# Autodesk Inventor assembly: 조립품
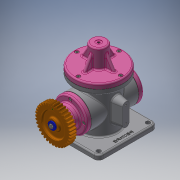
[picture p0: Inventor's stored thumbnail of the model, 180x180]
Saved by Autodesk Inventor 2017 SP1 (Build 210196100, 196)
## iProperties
Part Number: 조립품
Material: 일반
Document SubType Name: Assembly
Designer: 00-00
Author: 00-00
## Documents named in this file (21)
- C:\Users\00-00\Desktop\601206V1010\조립품.iam
- C:\Users\00-00\Desktop\601206V1010\E-링.ipt
- C:\Users\00-00\Desktop\601206V1010\가변스프링.ipt
- C:\Users\00-00\Desktop\601206V1010\개스킷 A.ipt
- C:\Users\00-00\Desktop\601206V1010\개스킷 B.ipt
- C:\Users\00-00\Desktop\601206V1010\덮개.ipt
- C:\Users\00-00\Desktop\601206V1010\뒤커버.ipt
- C:\Users\00-00\Desktop\601206V1010\링크.ipt
- C:\Users\00-00\Desktop\601206V1010\베어링 17 x 40 x 12.ipt
- C:\Users\00-00\Desktop\601206V1010\본체.ipt
- C:\Users\00-00\Desktop\601206V1010\볼트 M4 x 10.ipt
- C:\Users\00-00\Desktop\601206V1010\스퍼기어.ipt
- C:\Users\00-00\Desktop\601206V1010\슬라이더.ipt
- C:\Users\00-00\Desktop\601206V1010\앞커버.ipt
- C:\Users\00-00\Desktop\601206V1010\오일 실 17 30 8.ipt
- C:\Users\00-00\Desktop\601206V1010\와셔 4x16.ipt
- C:\Users\00-00\Desktop\601206V1010\육각 소켓 머리 볼트 M4 x 10.ipt
- C:\Users\00-00\Desktop\601206V1010\클레비스 핀 6 x 22.ipt
- 클레비스 핀 6 x 22.ipt
- C:\Users\00-00\Desktop\601206V1010\키 4 x 4 x 18.ipt
- C:\Users\00-00\Desktop\601206V1010\편심축.ipt
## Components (5 placed, 4 different names)
1. E-링:1
2. 가변스프링:1
3. 개스킷 A:1
4. 개스킷 B:1
5. 개스킷 A:2
